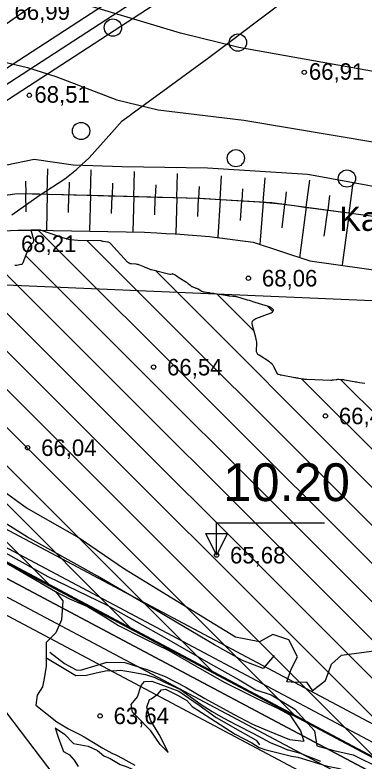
# Model space of a CAD drawing. Extents: x 532503 to 539665, y 6557663 to 6561526.
# Drawn here: x 535009.1 to 535060.8, y 6559752.1 to 6559862.6 of the extents above; entities that cross this region are included whole.
import ezdxf

# ---------------------------------------------------------------- set-up
doc = ezdxf.new("R2010")
doc.units = 0
for name, color, linetype in [('HALJASTUS', 7, 'Continuous'), ('HORISONTAAL-EH2000', 7, 'Continuous'), ('illumineerimisjooned', 7, 'Continuous'), ('jääkpaksus', 7, 'Continuous'), ('Kaevandatud ala', 7, 'Continuous'), ('Kaitsevöönd', 7, 'Continuous'), ('kataster', 7, 'Continuous'), ('KORGUS-EH2000', 7, 'Continuous'), ('Lõige', 7, 'Continuous'), ('ME_aktiivne', 7, 'Continuous'), ('PIIR_me', 7, 'Continuous'), ('Plokid', 7, 'Continuous'), ('RELJEEF', 7, 'Continuous'), ('TM_aktiivne', 7, 'Continuous')]:
    doc.layers.add(name, color=color, linetype=linetype)

# ---------------------------------------------------------------- blocks, each defined once
blk = doc.blocks.new('METS')
at = {"layer": 'HALJASTUS'}
blk.add_circle((0, 0), 0.8, dxfattribs=at)

msp = doc.modelspace()

# ---------------------------------------------------------------- linework, layer by layer
at = {"layer": 'HORISONTAAL-EH2000'}
for points in [[(535072.08, 6559852.43), (535042.23, 6559857.77), (535033.58, 6559859.93), (535016.45, 6559865.1), (535001.38, 6559870.04), (534994.05, 6559872.95), (534983.99, 6559877.9), (534964.33, 6559888.98), (534953.38, 6559894.3), (534947.66, 6559896.37), (534945.79, 6559896.76)], [(534983.62, 6559861.41), (534995.89, 6559858.28), (535002.31, 6559856.84), (535010.93, 6559854.84), (535015.15, 6559853.51), (535024.14, 6559850.04), (535030.28, 6559848.56), (535042.95, 6559847.02), (535069.4, 6559842.6), (535083.84, 6559840.56), (535091.09, 6559840.22), (535098.44, 6559840.55), (535113.09, 6559842.54), (535129.25, 6559845.19), (535150.59, 6559848.45), (535161.14, 6559850.59), (535196.02, 6559860.91), (535218.89, 6559866.28)]]:
    msp.add_lwpolyline(points, dxfattribs=at)
at = {"layer": 'illumineerimisjooned'}
for points in [[(534195.15, 6559981.19), (534198.98, 6559981.55), (535160.12, 6560071.77), (535418.53, 6559993.82), (535458.87, 6559929.25), (535494.63, 6559867.7), (535482.6, 6559826), (535251.74, 6559649.68), (535250.36, 6559648.53), (535180.45, 6559687.33), (534941.15, 6559814.59), (534876.93, 6559774.72), (534959.62, 6559531.32), (534733.77, 6559483.15), (534375.91, 6559461.87), (534195.51, 6559444.47)], [(535103.27, 6559501.74), (534971.34, 6559496.8), (534876.94, 6559774.72), (534941.15, 6559814.6), (535178.87, 6559688.17)], [(534960.71, 6559535.56), (534879.83, 6559773.69), (534941.24, 6559811.84), (535177.96, 6559685.93)]]:
    msp.add_lwpolyline(points, dxfattribs=at)
msp.add_lwpolyline([(534967.67, 6560049.69), (534974.15, 6559828.08), (535058.69, 6559883.05), (535223.5, 6560002.45), (535218.56, 6560049.92), (535415.93, 6559990.42), (535455.45, 6559927.19), (535490.31, 6559867.16), (535479.12, 6559828.38), (535249.57, 6559653.05), (535182.36, 6559690.84), (534940.99, 6559819.22), (534872.14, 6559776.44), (534954.37, 6559534.34), (534950.91, 6559533.67), (534733.22, 6559487.12), (534375.58, 6559465.86), (534199.95, 6559448.92), (533951.79, 6559660.13), (534200.21, 6559977.65), (534931.63, 6560046.31)], close=True, dxfattribs=at)
at = {"layer": 'jääkpaksus'}
msp.add_lwpolyline([(535038.92, 6559782.59), (535038.92, 6559787.39), (535054.92, 6559787.39)], dxfattribs=at)
msp.add_lwpolyline([(535038.92, 6559782.59), (535037.32, 6559785.79), (535040.52, 6559785.79)], close=True, dxfattribs=at)
at = {"layer": 'Kaevandatud ala'}
for p, q in [((534955.89, 6559847.79), (535038.68, 6559764.99)), ((534952.62, 6559845.41), (535026.6, 6559771.42)), ((534948.59, 6559843.77), (535014.52, 6559777.85)), ((534977.01, 6559832.32), (535050.77, 6559758.57)), ((534984.1, 6559830.9), (535062.85, 6559752.14)), ((535012.54, 6559830.74), (535123.27, 6559720.01)), ((534996.11, 6559830.2), (535087.02, 6559739.29)), ((534991.44, 6559829.21), (535074.93, 6559745.71)), ((535002.9, 6559829.07), (535099.1, 6559732.86)), ((535019.76, 6559829.17), (535135.35, 6559713.58)), ((535010.65, 6559826.97), (535111.19, 6559726.43)), ((535029.91, 6559824.68), (535147.44, 6559707.15)), ((535038.99, 6559821.26), (535044.47, 6559815.78)), ((535046.44, 6559819.46), (535047.24, 6559818.67)), ((535051.56, 6559808.68), (535159.52, 6559700.73)), ((535057.33, 6559808.57), (535171.6, 6559694.3))]:
    msp.add_line(p, q, dxfattribs=at)
for points in [[(535011.52, 6559830.74), (535011.49, 6559830.71), (535011.47, 6559830.66), (535011.48, 6559830.6), (535011.82, 6559829.35), (535011.84, 6559829.2), (535011.83, 6559829.07), (535011.78, 6559828.94), (535011.69, 6559828.82), (535011.28, 6559828.35), (535011.19, 6559828.24), (535011.1, 6559828.11), (535011.03, 6559827.97), (535010.97, 6559827.83), (535010.25, 6559825.88), (535010.2, 6559825.78), (535010.13, 6559825.71), (535010.05, 6559825.65), (535009.95, 6559825.62), (535009.37, 6559825.49), (535009.34, 6559825.48), (535009.3, 6559825.48), (535009.26, 6559825.48), (535009.23, 6559825.49), (535009.08, 6559825.51)], [(535012.88, 6559830.73), (535012.02, 6559830.75), (535011.52, 6559830.74)], [(535060.89, 6559808.02), (535060.09, 6559808.13), (535059.89, 6559808.16), (535059.69, 6559808.19), (535059.49, 6559808.22), (535059.28, 6559808.26), (535057.87, 6559808.52), (535057.77, 6559808.54), (535057.67, 6559808.55), (535057.56, 6559808.56), (535057.46, 6559808.57), (535057.03, 6559808.59), (535056.93, 6559808.59), (535056.83, 6559808.59), (535056.73, 6559808.58), (535056.64, 6559808.57), (535056.24, 6559808.51), (535056.14, 6559808.49), (535056.04, 6559808.49), (535055.94, 6559808.48), (535055.84, 6559808.48), (535052.3, 6559808.6), (535052.15, 6559808.61), (535052, 6559808.62), (535051.85, 6559808.64), (535051.7, 6559808.66), (535051.1, 6559808.76), (535050.96, 6559808.78), (535050.81, 6559808.81), (535050.66, 6559808.84), (535050.51, 6559808.86), (535048.47, 6559809.25), (535048.42, 6559809.26), (535048.37, 6559809.27), (535048.33, 6559809.28), (535048.28, 6559809.3), (535048.1, 6559809.35), (535048.05, 6559809.37), (535048.01, 6559809.4), (535047.98, 6559809.43), (535047.96, 6559809.47), (535047.35, 6559810.58), (535047.23, 6559810.77), (535047.09, 6559810.94), (535046.93, 6559811.09), (535046.75, 6559811.22), (535045.22, 6559812.19), (535045.04, 6559812.33), (535044.92, 6559812.5), (535044.85, 6559812.69), (535044.83, 6559812.92), (535044.87, 6559813.88), (535044.87, 6559814.12), (535044.85, 6559814.35), (535044.81, 6559814.59), (535044.75, 6559814.82), (535044.22, 6559816.61), (535044.17, 6559816.96), (535044.24, 6559817.24), (535044.43, 6559817.47), (535044.74, 6559817.63), (535047.02, 6559818.46), (535047.07, 6559818.49), (535047.12, 6559818.52), (535047.16, 6559818.56), (535047.19, 6559818.6), (535047.36, 6559818.86), (535047.37, 6559818.88), (535047.37, 6559818.9), (535047.36, 6559818.91), (535047.35, 6559818.93), (535047.28, 6559819), (535047.26, 6559819.01), (535047.24, 6559819.03), (535047.22, 6559819.05), (535047.2, 6559819.06), (535047.09, 6559819.15), (535047.06, 6559819.17), (535047.04, 6559819.19), (535047.01, 6559819.2), (535046.98, 6559819.22), (535046.79, 6559819.33), (535046.75, 6559819.35), (535046.71, 6559819.37), (535046.66, 6559819.39), (535046.62, 6559819.41), (535044.64, 6559820.03), (535044.36, 6559820.12), (535044.08, 6559820.2), (535043.8, 6559820.29), (535043.52, 6559820.37), (535041.94, 6559820.84), (535041.89, 6559820.86), (535041.84, 6559820.87), (535041.79, 6559820.88), (535041.74, 6559820.88), (535041.53, 6559820.89), (535041.48, 6559820.9), (535041.43, 6559820.9), (535041.38, 6559820.91), (535041.33, 6559820.91), (535040.9, 6559820.96), (535040.81, 6559820.97), (535040.72, 6559820.98), (535040.63, 6559820.99), (535040.54, 6559821.01), (535038.72, 6559821.3), (535038.65, 6559821.31), (535038.57, 6559821.32), (535038.5, 6559821.34), (535038.42, 6559821.35), (535038, 6559821.41), (535037.99, 6559821.42), (535037.97, 6559821.42), (535037.96, 6559821.42), (535037.95, 6559821.43), (535037.89, 6559821.44), (535037.88, 6559821.44), (535037.87, 6559821.45), (535037.86, 6559821.45), (535037.85, 6559821.45), (535037.8, 6559821.46), (535037.78, 6559821.46), (535037.75, 6559821.46), (535037.13, 6559821.52), (535037.02, 6559821.54), (535036.92, 6559821.57), (535036.82, 6559821.61), (535036.72, 6559821.66), (535036.18, 6559821.98), (535036.1, 6559822.03), (535036.01, 6559822.07), (535035.92, 6559822.11), (535035.82, 6559822.14), (535035.45, 6559822.27), (535035.36, 6559822.31), (535035.27, 6559822.35), (535035.19, 6559822.4), (535035.11, 6559822.46), (535034.79, 6559822.74), (535034.71, 6559822.81), (535034.63, 6559822.88), (535034.55, 6559822.94), (535034.46, 6559822.99), (535033.36, 6559823.69), (535033.31, 6559823.73), (535033.25, 6559823.76), (535033.2, 6559823.8), (535033.15, 6559823.83), (535032.95, 6559823.97), (535032.9, 6559824.01), (535032.85, 6559824.04), (535032.8, 6559824.07), (535032.74, 6559824.1), (535032.5, 6559824.22), (535032.46, 6559824.24), (535032.42, 6559824.25), (535032.38, 6559824.25), (535032.33, 6559824.23), (535032.16, 6559824.17), (535032.12, 6559824.16), (535032.07, 6559824.16), (535032.03, 6559824.16), (535031.99, 6559824.16), (535029.29, 6559824.84), (535029.19, 6559824.87), (535029.08, 6559824.9), (535028.98, 6559824.94), (535028.88, 6559824.99), (535028.48, 6559825.17), (535028.38, 6559825.22), (535028.28, 6559825.27), (535028.18, 6559825.31), (535028.07, 6559825.35), (535027.55, 6559825.55), (535027.42, 6559825.59), (535027.3, 6559825.63), (535027.17, 6559825.65), (535027.04, 6559825.67), (535026.31, 6559825.73), (535026.15, 6559825.76), (535026.01, 6559825.82), (535025.88, 6559825.9), (535025.76, 6559826.01), (535023.2, 6559828.76), (535023.12, 6559828.84), (535023.03, 6559828.9), (535022.93, 6559828.94), (535022.82, 6559828.96), (535022.15, 6559829.06), (535022.15, 6559829.06), (535022.14, 6559829.06), (535022.14, 6559829.06), (535022.13, 6559829.06), (535022.11, 6559829.05), (535022.1, 6559829.05), (535022.1, 6559829.05), (535022.09, 6559829.05), (535022.09, 6559829.05), (535021.92, 6559829.11), (535021.89, 6559829.12), (535021.86, 6559829.13), (535021.83, 6559829.13), (535021.8, 6559829.14), (535018.4, 6559829.2), (535017.83, 6559829.23), (535017.26, 6559829.31), (535016.7, 6559829.43), (535016.16, 6559829.6), (535012.88, 6559830.73)], [(534874.54, 6559775.58), (534941.07, 6559816.91), (535181.4, 6559689.09)]]:
    msp.add_lwpolyline(points, dxfattribs=at)
at = {"layer": 'Kaitsevöönd'}
msp.add_lwpolyline([(535000, 6559953.12), (535049.42, 6559992.99), (535086.86, 6560014.83), (535132.35, 6560020.86), (535156.39, 6560022.14), (535166.68, 6560016.65), (535179.42, 6560020.55), (535204.9, 6560018.21), (535209.94, 6560002.96), (535206.22, 6560000.36), (534981.72, 6559843), (534978.44, 6559955.29), (534988.83, 6559966.07)], close=True, dxfattribs=at)
at = {"layer": 'kataster'}
for points in [[(533947.7, 6559658.95), (533949.2, 6559955.8), (534198.28, 6559979.48), (535159.89, 6560069.73), (535417.31, 6559992.13), (535457.22, 6559928.24), (535504.86, 6559846.09), (535250.3, 6559650.84), (535181.52, 6559689.04), (534941.15, 6559817.08), (534874.65, 6559775.26), (534957.01, 6559532.73), (534735.22, 6559485.45), (534375.71, 6559463.85), (534199.28, 6559446.9), (534122.84, 6559439.44), (534110.45, 6559447.36), (534092.53, 6559453.94), (534085.13, 6559454.75)], [(534957.01, 6559532.73), (534874.65, 6559775.26), (534941.15, 6559817.08), (535181.52, 6559689.04), (535104.64, 6559499.79), (534969.93, 6559494.75)]]:
    msp.add_lwpolyline(points, close=True, dxfattribs=at)
at = {"layer": 'KORGUS-EH2000'}
for centre in [(535051.9, 6559854.11), (535011.21, 6559850.71), (535043.64, 6559823.61), (535029.6, 6559810.44), (535055.03, 6559803.21), (535010.96, 6559798.5), (535038.92, 6559782.59), (535021.68, 6559758.78)]:
    msp.add_circle(centre, 0.32, dxfattribs=at)
at = {"layer": 'Lõige'}
msp.add_lwpolyline([(533917.43, 6559650.43), (533949.04, 6559659.85), (534215.74, 6559786.31), (534470.46, 6559695.5), (534707.91, 6559763.06), (534929.16, 6559826.01), (535198.18, 6559814.49), (535305.66, 6559887.85), (535520.8, 6559960.87), (535543.92, 6559971)], dxfattribs=at)
at = {"layer": 'ME_aktiivne'}
msp.add_lwpolyline([(534874.54, 6559775.58), (534941.07, 6559816.91), (535181.4, 6559689.09), (535131.71, 6559566.56), (534957, 6559532.81)], close=True, dxfattribs=at)
at = {"layer": 'PIIR_me'}
msp.add_lwpolyline([(534441.63, 6560002.32), (534688.17, 6560025.46), (534931.44, 6560048.3), (534969.61, 6560051.88), (534976.05, 6559831.7), (535057.56, 6559884.7), (535221.39, 6560003.39), (535216.26, 6560052.7), (535417.23, 6559992.12), (535457.16, 6559928.22), (535492.47, 6559867.43), (535480.86, 6559827.19), (535250.12, 6559650.95), (535250.12, 6559650.95), (535181.4, 6559689.09), (534941.07, 6559816.91), (534874.54, 6559775.58), (534957, 6559532.81), (534951.31, 6559531.71), (534733.49, 6559485.13), (534485.11, 6559470.37)], dxfattribs=at)
at = {"layer": 'Plokid'}
for points in [[(534971.81, 6560045.13), (534977.95, 6559835.31), (535052.03, 6559883.49)], [(535008.62, 6559833), (535012.69, 6559835.84), (535016.47, 6559838.31), (535018.19, 6559839.73), (535018.95, 6559840.41), (535020.05, 6559841.43), (535023.44, 6559845.22), (535024.97, 6559846.94), (535026.01, 6559847.67), (535026.25, 6559847.86), (535029.55, 6559850.26), (535030.95, 6559851.31), (535037.8, 6559856.32), (535041.13, 6559858.84), (535044.78, 6559861.59), (535047.95, 6559863.94)], [(535473.83, 6559827.36), (535249.73, 6559656.2), (535183.5, 6559692.96), (534940.9, 6559821.97), (534869.24, 6559777.47), (534950.46, 6559538.37)], [(534961.53, 6559540.61), (534882.72, 6559772.65), (534941.33, 6559809.07), (535174.93, 6559684.83)]]:
    msp.add_lwpolyline(points, dxfattribs=at)
at = {"layer": 'RELJEEF'}
for p, q in [((535013.87, 6559836.06), (535013.96, 6559839.81)), ((535020.27, 6559835.91), (535020.36, 6559839.68)), ((535026.66, 6559835.73), (535026.77, 6559839.41)), ((535033.06, 6559835.56), (535033.16, 6559839.1)), ((535039.45, 6559835.27), (535039.67, 6559838.78)), ((535045.84, 6559834.89), (535046.14, 6559838.47)), ((535010.62, 6559838.01), (535010.67, 6559836.14)), ((535017.11, 6559837.86), (535017.07, 6559835.98)), ((535023.52, 6559837.69), (535023.47, 6559835.82)), ((535029.91, 6559837.45), (535029.86, 6559835.64)), ((535052.19, 6559834.13), (535052.74, 6559838.15)), ((535058.54, 6559833.27), (535059.14, 6559837.72)), ((535036.34, 6559837.2), (535036.26, 6559835.46)), ((535042.76, 6559836.85), (535042.65, 6559835.08)), ((535049.25, 6559836.43), (535049.02, 6559834.55)), ((535010.74, 6559833.44), (535010.67, 6559836.14)), ((535013.87, 6559836.06), (535013.74, 6559830.77)), ((535017, 6559833.36), (535017.07, 6559835.98)), ((535020.27, 6559835.91), (535020.13, 6559830.67)), ((535023.39, 6559833.22), (535023.47, 6559835.82)), ((535026.66, 6559835.73), (535026.52, 6559830.52)), ((535029.79, 6559833), (535029.86, 6559835.64)), ((535033.06, 6559835.56), (535032.91, 6559830.18)), ((535036.14, 6559832.74), (535036.26, 6559835.46)), ((535039.45, 6559835.27), (535039.11, 6559829.63)), ((535042.47, 6559832.14), (535042.65, 6559835.08)), ((535055.66, 6559835.84), (535055.37, 6559833.7)), ((535045.84, 6559834.89), (535045.32, 6559828.59)), ((535048.61, 6559831.07), (535049.02, 6559834.55)), ((535052.19, 6559834.13), (535051.19, 6559826.64)), ((535054.85, 6559829.85), (535055.37, 6559833.7)), ((535058.54, 6559833.27), (535057.5, 6559825.59))]:
    msp.add_line(p, q, dxfattribs=at)
for points in [[(535069.95, 6559835.78), (535052.44, 6559838.97), (535037.57, 6559839.89), (535024.94, 6559840.11), (535017.68, 6559840.37), (535011.93, 6559841.19), (535006.42, 6559840.05), (534999.71, 6559838.7), (534996.01, 6559837.2), (534989.21, 6559837.06), (534985.33, 6559838.06), (534983.65, 6559843.25), (534981.41, 6559851.84), (534978.36, 6559863.2)], [(534937.43, 6559842), (534947.92, 6559848.33), (534960.17, 6559856.21), (534968.41, 6559860.34), (534973.25, 6559862.61), (534975.66, 6559862.6), (534976.11, 6559859.63), (534977.82, 6559853.91), (534979.05, 6559847.95), (534981.39, 6559840.54), (534983.69, 6559835.19), (534989.39, 6559833.61), (535000.96, 6559834.93), (535009.43, 6559836.17), (535020.41, 6559835.9), (535036.19, 6559835.47), (535047.11, 6559834.81), (535088.5, 6559829.24)], [(535006.93, 6559835.8), (535009.43, 6559836.17), (535011.92, 6559836.11), (535012.72, 6559836.09), (535014.04, 6559836.06), (535016.27, 6559836), (535017.81, 6559835.97), (535019.78, 6559835.92), (535022.9, 6559835.83), (535025.13, 6559835.77), (535028.6, 6559835.68), (535030.19, 6559835.63), (535032.53, 6559835.57), (535034.57, 6559835.51), (535036.49, 6559835.45), (535041.09, 6559835.17), (535045.24, 6559834.92), (535047.93, 6559834.7), (535050.44, 6559834.36), (535051.94, 6559834.16), (535053.17, 6559833.99), (535059.91, 6559833.09), (535066.91, 6559832.15)], [(534996.8, 6559830.2), (535009.56, 6559830.72), (535012.02, 6559830.75), (535028.24, 6559830.43), (535030.1, 6559830.33), (535031.48, 6559830.25), (535032.78, 6559830.18), (535033.48, 6559830.15), (535037.89, 6559829.8), (535044.36, 6559828.93), (535052.72, 6559826.2), (535064.98, 6559824.45)], [(535047.46, 6559767.7), (535045.82, 6559765.82), (535042.78, 6559766.98), (535038.61, 6559769.3), (535030.55, 6559774.1), (535021.31, 6559779.45), (535010.92, 6559785.27), (535000.17, 6559791.97), (534991.4, 6559795.79), (534984.04, 6559799.05), (534975.41, 6559803.18), (534969.55, 6559806.48), (534966.31, 6559808.82), (534964.79, 6559810.62), (534963.73, 6559811.54), (534962.35, 6559812.62), (534958.85, 6559814.63)], [(534943.93, 6559811.51), (534948.93, 6559811.75), (534950.16, 6559811.85), (534952.89, 6559811.07), (534955.47, 6559809.91), (534958.26, 6559808.54), (534965.18, 6559805.27), (534971.35, 6559801.96), (534975.64, 6559799.59), (534980.75, 6559796.99), (534986.64, 6559793.92), (534995.99, 6559789.2), (535003.32, 6559785.09), (535008.04, 6559782.72), (535013.96, 6559779.43), (535022.75, 6559775.16), (535031.5, 6559770.26), (535038.01, 6559766.49), (535042.28, 6559764.12), (535044.76, 6559762.65), (535046.99, 6559761.91), (535050.53, 6559759.79), (535053.4, 6559756.56), (535053.75, 6559754.36)], [(535053.18, 6559762.47), (535052.27, 6559763.78), (535050.54, 6559763.7), (535049.33, 6559763.83), (535049.98, 6559765.69), (535050.88, 6559767.51), (535049.61, 6559770.05), (535047.23, 6559770.85), (535045.28, 6559769.77), (535043.51, 6559770.09), (535041.74, 6559770.45), (535025.32, 6559780.52), (535018.31, 6559785.32), (535010.73, 6559789.61), (535004.18, 6559794.34)], [(535002.05, 6559784.76), (535015.06, 6559777.19), (535016.18, 6559775.84), (535015.96, 6559772.99), (535015.13, 6559771.09), (535013.68, 6559769.65), (535013.71, 6559766.11), (535013.37, 6559764.08), (535013.16, 6559763.06), (535012.35, 6559761.83), (535012.17, 6559760.35), (535015.3, 6559757.88), (535017.02, 6559756.84), (535018.68, 6559756.03), (535019.33, 6559755.68), (535022.11, 6559753.99), (535023.42, 6559753.23), (535024.03, 6559752.99), (535025.05, 6559752.44), (535026.82, 6559751.5)], [(535015.06, 6559777.19), (535017.16, 6559776.1), (535019.81, 6559774.99), (535022.12, 6559773.61), (535024.4, 6559772.15), (535028.13, 6559770.28), (535031.84, 6559768.47), (535036.39, 6559765.84), (535040.15, 6559763.71), (535045.06, 6559761.26), (535047.92, 6559759.92), (535049.76, 6559758.94), (535051.34, 6559756.56), (535051.84, 6559755.04)], [(535053.07, 6559762.47), (535055.03, 6559764), (535055.94, 6559766.45), (535057.42, 6559767.79), (535063.73, 6559768.6), (535066.85, 6559768.17), (535070.34, 6559768.4), (535072.47, 6559768.37), (535076.58, 6559767.63), (535079, 6559767.47), (535082.41, 6559768.67), (535084.89, 6559769.97), (535087.6, 6559770.86), (535090.63, 6559770.21), (535091.66, 6559768.87), (535092.58, 6559767.66), (535094.16, 6559765.91), (535095.24, 6559764.47), (535095.72, 6559762.97), (535096.31, 6559761.48), (535096.72, 6559760.2), (535097.04, 6559759.51), (535097, 6559756.75)], [(535014.26, 6559768.24), (535016.42, 6559766.54), (535018.16, 6559765.59), (535018.78, 6559765.55), (535022.75, 6559766.74), (535025.33, 6559766.68), (535028.75, 6559765.61), (535031.32, 6559764.61), (535034.27, 6559763.08), (535037.18, 6559761.37), (535041.41, 6559759.03), (535044.26, 6559757.57), (535046.47, 6559756.62), (535049.71, 6559755.28), (535051.84, 6559755.04)], [(535013.65, 6559767.44), (535017.11, 6559765.37), (535018.11, 6559764.76), (535019.67, 6559764.82), (535021.1, 6559765.14), (535022.73, 6559765.49), (535023.57, 6559765.43), (535024.75, 6559765.55), (535025.96, 6559765.34), (535028.42, 6559764.91), (535029.78, 6559764.45), (535031.1, 6559763.81), (535033.57, 6559762.7), (535036.64, 6559760.47), (535038.28, 6559759.41), (535039.89, 6559758.51), (535041.86, 6559757.47), (535044.39, 6559756.19), (535045.05, 6559755.84), (535046.87, 6559754.84), (535048.45, 6559754.17), (535049.4, 6559753.77), (535049.54, 6559753.73), (535051.28, 6559753.23), (535054.31, 6559752.07)], [(535031.74, 6559753.37), (535030.57, 6559754.55), (535029.18, 6559756.58), (535027.11, 6559758.71), (535026.47, 6559759.31), (535026.29, 6559760.48), (535027.24, 6559761.58), (535027.78, 6559763.28), (535028.26, 6559763.86), (535029.36, 6559763.9), (535033.32, 6559762.42), (535036.34, 6559760.35), (535038.86, 6559758.54), (535042.44, 6559756.5), (535044.78, 6559755.19), (535045.28, 6559754.5)], [(535031.74, 6559753.37), (535030.87, 6559755.2), (535030.41, 6559756.03), (535029.13, 6559758.12), (535028.6, 6559760.09), (535028.99, 6559761.18), (535029.26, 6559761.3), (535030.24, 6559761.97), (535030.76, 6559762.63), (535031.39, 6559762.73), (535033.24, 6559761.81), (535034.52, 6559761.05), (535035.32, 6559760.19), (535038.07, 6559758.41), (535041.69, 6559756.05), (535044.16, 6559754.8), (535045.25, 6559754.1), (535046.06, 6559753.82), (535050.02, 6559752.79), (535050.93, 6559752.68), (535055.15, 6559751.37), (535056.88, 6559751.01), (535061.59, 6559749.6)], [(535007.83, 6559759.24), (535015.9, 6559748.56), (535017.48, 6559737.98), (535018.3, 6559737.85), (535024.43, 6559734.99), (535031.27, 6559731.99), (535038.21, 6559723.99), (535043.82, 6559714.66), (535047.67, 6559707.01), (535061.18, 6559696.44), (535066.27, 6559693.12), (535073.71, 6559686.85), (535077.03, 6559683.83), (535080.74, 6559680.56), (535085.93, 6559676.26), (535091.06, 6559674.47)], [(535015.05, 6559757), (535016.4, 6559756.07), (535017.77, 6559754.69), (535019.94, 6559754.29), (535021.3, 6559753.64), (535022.22, 6559752.84), (535023.16, 6559752.44), (535024.66, 6559751.57), (535025.54, 6559751.28), (535027, 6559750.66), (535028.46, 6559750.62)], [(535015.05, 6559757), (535015.5, 6559755.62), (535016.04, 6559754.12), (535016.29, 6559753.51), (535017.16, 6559753.02), (535017.87, 6559752.23), (535018.45, 6559751.3)], [(535053.75, 6559754.36), (535056.29, 6559753.63), (535059.12, 6559753), (535063.15, 6559751.01), (535069.29, 6559748.48), (535072.8, 6559746.04), (535076.06, 6559744.28), (535079.98, 6559742.66), (535081.06, 6559744.3), (535083.02, 6559746.42), (535086.76, 6559747.65), (535089.31, 6559749.33), (535091.15, 6559751.64), (535092.64, 6559753.17), (535093.99, 6559754.09), (535095.7, 6559755.92), (535097, 6559756.75)]]:
    msp.add_lwpolyline(points, dxfattribs=at)
at = {"layer": 'TM_aktiivne'}
for points in [[(535159.92, 6560069.74), (535417.23, 6559992.12), (535457.16, 6559928.22), (535492.47, 6559867.43), (535480.86, 6559827.19), (535250.49, 6559651.24), (535250.13, 6559650.94), (535181.4, 6559689.09), (534941.07, 6559816.9), (534874.53, 6559775.58), (534957, 6559532.81), (534733.5, 6559485.14), (534375.75, 6559463.86), (534199.32, 6559446.85), (534124.95, 6559439.68), (533949.03, 6559659.85), (533949.15, 6559955.79), (534199.17, 6559979.56)], [(534874.54, 6559775.58), (534941.07, 6559816.91), (535181.4, 6559689.09), (535104.64, 6559499.79), (534969.93, 6559494.75)]]:
    msp.add_lwpolyline(points, close=True, dxfattribs=at)

# ---------------------------------------------------------------- block references
at = {"layer": 'HALJASTUS', "xscale": 1.6, "yscale": 1.6000000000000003}
for p in [(535023.58, 6559860.74), (535042.08, 6559858.52), (535018.87, 6559845.42), (535041.78, 6559841.39), (535058.22, 6559838.38)]:
    msp.add_blockref('METS', p, dxfattribs=at)

# ---------------------------------------------------------------- texts
at = {"layer": 'HALJASTUS'}
msp.add_text('Katend', height=3.6, dxfattribs=at).set_placement((535057.09, 6559830.62))
at = {"layer": 'jääkpaksus'}
msp.add_text('10.20 ', height=5.6, dxfattribs=at).set_placement((535039.92, 6559790.59))
at = {"layer": 'KORGUS-EH2000'}
for s, p in [('66,99', (535009.02, 6559861.88)), ('66,91', (535052.59, 6559853.01)), ('68,51', (535011.96, 6559849.61)), ('68,21 ', (535009.98, 6559827.49)), ('68,06 ', (535045.64, 6559822.39)), ('66,54 ', (535031.6, 6559809.21)), ('66,43 ', (535057.03, 6559801.98)), ('66,04 ', (535012.96, 6559797.28)), ('65,68 ', (535040.92, 6559781.36)), ('63,64 ', (535023.68, 6559757.56))]:
    msp.add_text(s, height=2.45, dxfattribs=at).set_placement(p)

doc.saveas('drawing.dxf')
